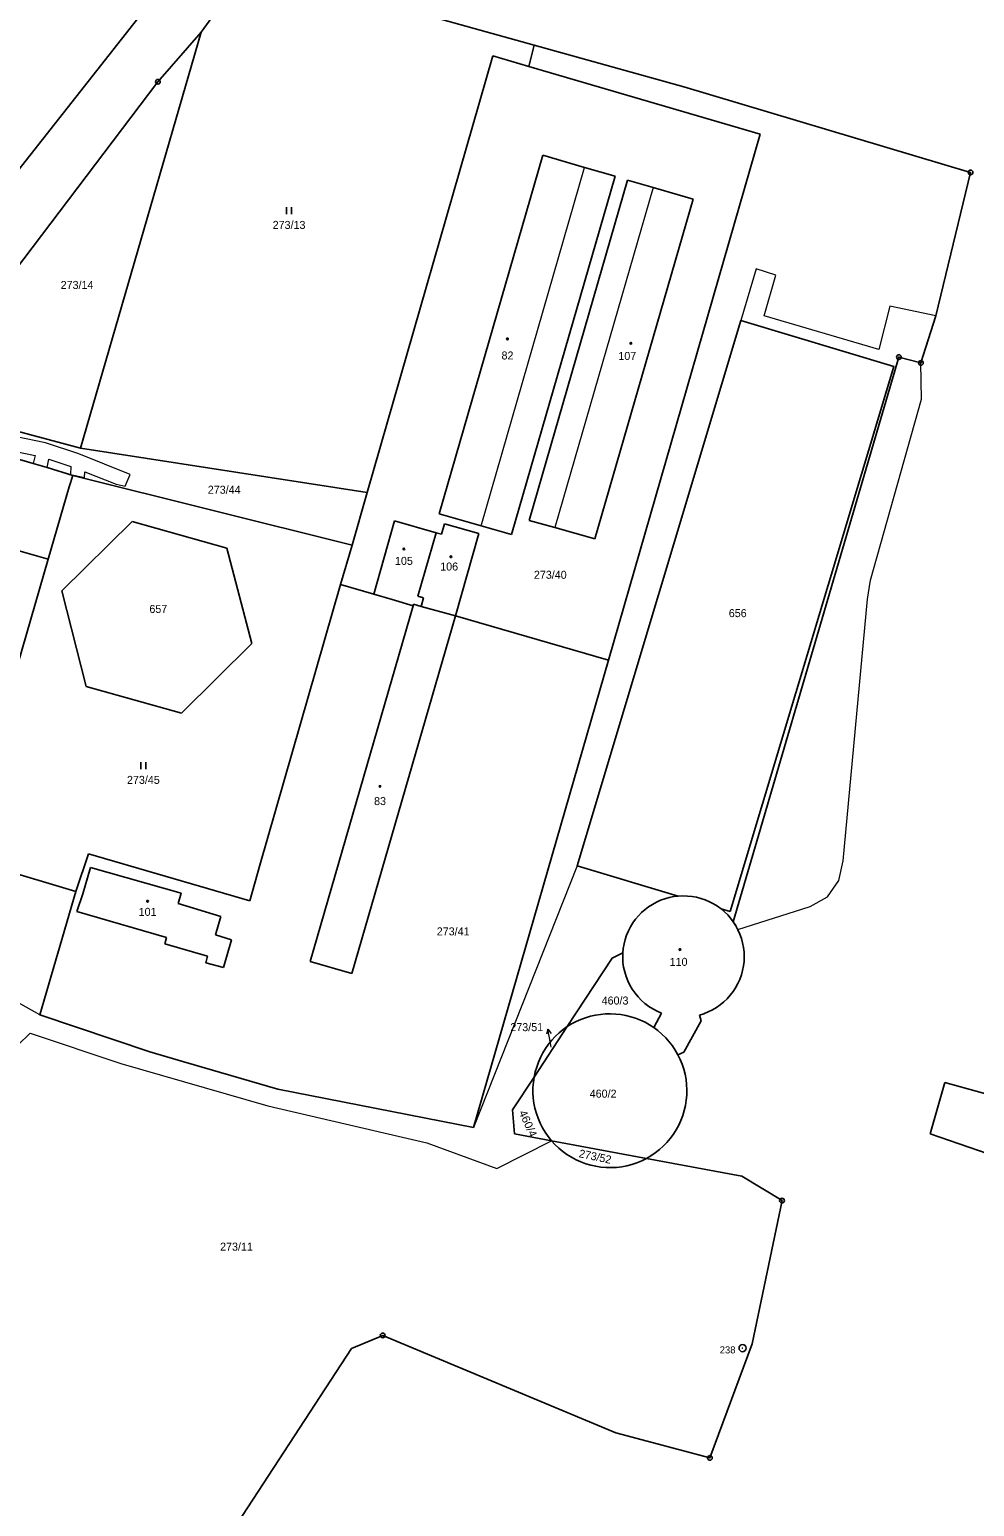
# Model space of a CAD drawing. Extents: x -759947 to -757003, y -1019641 to -1017100.
# Drawn here: x -758700 to -758499.4, y -1018436.3 to -1018122.6 of the extents above; entities that cross this region are included whole.
import ezdxf
from ezdxf.enums import TextEntityAlignment as Align

# ---------------------------------------------------------------- set-up
doc = ezdxf.new("R2010")
doc.units = 0
doc.header["$LTSCALE"] = 0.68
for name, color, linetype, lineweight in [('1', 7, 'Continuous', 25), ('13', 7, 'Continuous', 13), ('3', 7, 'Continuous', 25), ('4', 7, 'Continuous', 13), ('5', 7, 'Continuous', 25), ('7', 7, 'Continuous', 13), ('8', 7, 'Continuous', 25)]:
    doc.layers.add(name, color=color, linetype=linetype, lineweight=lineweight)
doc.layers.add('2', color=7, linetype='Continuous')

msp = doc.modelspace()

# ---------------------------------------------------------------- linework, layer by layer
at = {"layer": '1'}
for p, q in [((-758736.22, -1018195.55), (-758665.13, -1018105.17)), ((-758653.11, -1018108.83), (-758663.54, -1018123.19)), ((-758620.1, -1018118.37), (-758592.84, -1018125.96)), ((-758689.17, -1018211.55), (-758663.54, -1018123.19)), ((-758663.54, -1018123.19), (-758672.72, -1018133.73)), ((-758592.84, -1018125.96), (-758594, -1018130.48)), ((-758592.84, -1018125.96), (-758561.11, -1018134.79)), ((-758601.62, -1018128.24), (-758628.32, -1018220.98)), ((-758594, -1018130.48), (-758601.62, -1018128.24)), ((-758544.89, -1018144.88), (-758594, -1018130.48)), ((-758672.72, -1018133.73), (-758724.51, -1018202.05)), ((-758500.24, -1018152.97), (-758561.11, -1018134.79)), ((-758577.08, -1018256.57), (-758544.89, -1018144.88)), ((-758591.02, -1018149.28), (-758613.02, -1018225.48)), ((-758582.19, -1018151.92), (-758591.02, -1018149.28)), ((-758575.69, -1018153.75), (-758582.19, -1018151.92)), ((-758597.66, -1018229.89), (-758575.69, -1018153.75)), ((-758593.91, -1018226.88), (-758573.04, -1018154.62)), ((-758573.04, -1018154.62), (-758567.58, -1018156.21)), ((-758507.63, -1018183.46), (-758500.24, -1018152.97)), ((-758567.58, -1018156.21), (-758559.12, -1018158.67)), ((-758559.12, -1018158.67), (-758579.95, -1018230.83)), ((-758583.73, -1018300.25), (-758549.02, -1018184.43)), ((-758549.02, -1018184.43), (-758516.53, -1018194.17)), ((-758510.76, -1018193.44), (-758507.63, -1018183.46)), ((-758515.43, -1018192.19), (-758550.6, -1018312.14)), ((-758515.43, -1018192.19), (-758510.76, -1018193.44)), ((-758516.53, -1018194.17), (-758551.23, -1018309.99)), ((-758689.17, -1018211.55), (-758724.51, -1018202.05)), ((-758689.17, -1018211.55), (-758628.32, -1018220.98)), ((-758706.19, -1018212.74), (-758699.16, -1018214.78)), ((-758699.16, -1018214.78), (-758696.23, -1018215.67)), ((-758696.23, -1018215.67), (-758690.8, -1018217.33)), ((-758690.8, -1018217.33), (-758691.52, -1018219.77)), ((-758690.8, -1018217.33), (-758631.52, -1018232.12)), ((-758691.52, -1018219.77), (-758695.99, -1018235.12)), ((-758628.32, -1018220.98), (-758631.52, -1018232.12)), ((-758678.2, -1018227.14), (-758693.13, -1018241.87)), ((-758658.1, -1018232.78), (-758678.2, -1018227.14)), ((-758622.47, -1018227), (-758626.91, -1018242.56)), ((-758613.68, -1018229.51), (-758622.47, -1018227)), ((-758613.02, -1018225.48), (-758604.14, -1018228.03)), ((-758588.45, -1018228.43), (-758593.91, -1018226.88)), ((-758613.68, -1018229.51), (-758617.56, -1018242.97)), ((-758613.68, -1018229.51), (-758612.52, -1018229.84)), ((-758612.52, -1018229.84), (-758611.89, -1018227.63)), ((-758611.89, -1018227.63), (-758604.59, -1018229.68)), ((-758604.59, -1018229.68), (-758609.56, -1018247.18)), ((-758604.14, -1018228.03), (-758597.66, -1018229.89)), ((-758579.95, -1018230.83), (-758588.45, -1018228.43)), ((-758702.45, -1018233.28), (-758695.99, -1018235.12)), ((-758652.8, -1018253.02), (-758658.1, -1018232.78)), ((-758631.52, -1018232.12), (-758633.95, -1018240.53)), ((-758695.99, -1018235.12), (-758702.48, -1018257.43)), ((-758693.13, -1018241.87), (-758687.95, -1018262.19)), ((-758633.95, -1018240.53), (-758651.06, -1018300.15)), ((-758626.91, -1018242.56), (-758633.95, -1018240.53)), ((-758623.03, -1018243.68), (-758626.91, -1018242.56)), ((-758617.56, -1018242.97), (-758616.36, -1018243.3)), ((-758640.38, -1018320.61), (-758618.55, -1018245)), ((-758618.55, -1018245), (-758623.03, -1018243.68)), ((-758618.46, -1018244.71), (-758618.55, -1018245)), ((-758616.87, -1018245.15), (-758618.46, -1018244.71)), ((-758616.36, -1018243.3), (-758616.87, -1018245.15)), ((-758616.87, -1018245.15), (-758609.56, -1018247.18)), ((-758631.57, -1018323.1), (-758609.56, -1018247.18)), ((-758609.56, -1018247.18), (-758577.08, -1018256.57)), ((-758667.73, -1018267.8), (-758652.8, -1018253.02)), ((-758605.7, -1018355.81), (-758577.08, -1018256.57)), ((-758687.95, -1018262.19), (-758667.73, -1018267.8)), ((-758714.48, -1018298.45), (-758690.12, -1018305.73)), ((-758687.47, -1018297.72), (-758690.12, -1018305.73)), ((-758687.47, -1018297.72), (-758653.21, -1018307.72)), ((-758687.03, -1018300.58), (-758688.63, -1018306.18)), ((-758653.21, -1018307.72), (-758651.06, -1018300.15)), ((-758562.26, -1018306.69), (-758583.73, -1018300.25)), ((-758690.12, -1018305.73), (-758697.77, -1018331.94)), ((-758688.63, -1018306.18), (-758689.94, -1018309.94)), ((-758659.39, -1018311.02), (-758668.43, -1018308.27)), ((-758689.94, -1018309.94), (-758670.87, -1018315.5)), ((-758660.52, -1018314.91), (-758659.39, -1018311.02)), ((-758551.23, -1018309.99), (-758553.18, -1018309.41)), ((-758660.52, -1018314.91), (-758657.07, -1018315.95)), ((-758670.87, -1018315.5), (-758671.24, -1018316.83)), ((-758671.24, -1018316.83), (-758662.19, -1018319.47)), ((-758658.82, -1018321.89), (-758657.07, -1018315.95)), ((-758662.19, -1018319.47), (-758662.57, -1018320.83)), ((-758662.57, -1018320.83), (-758658.82, -1018321.89)), ((-758631.57, -1018323.1), (-758640.38, -1018320.61)), ((-758576.27, -1018319.85), (-758585.84, -1018334.42)), ((-758574.04, -1018318.75), (-758576.27, -1018319.85)), ((-758674.43, -1018339.76), (-758697.77, -1018331.94)), ((-758565.84, -1018331.55), (-758567.47, -1018334.6)), ((-758561.1, -1018339.83), (-758557.39, -1018333.21)), ((-758557.39, -1018333.21), (-758557.77, -1018331.97)), ((-758585.84, -1018334.42), (-758592.86, -1018345.12)), ((-758667.18, -1018341.89), (-758674.43, -1018339.76)), ((-758562.34, -1018340.38), (-758561.1, -1018339.83)), ((-758647.29, -1018347.73), (-758667.18, -1018341.89)), ((-758592.86, -1018345.12), (-758597.45, -1018352.12)), ((-758505.66, -1018346.27), (-758508.84, -1018357.21)), ((-758485.33, -1018351.92), (-758505.66, -1018346.27)), ((-758647.29, -1018347.73), (-758605.7, -1018355.81)), ((-758597.03, -1018357.19), (-758597.45, -1018352.12)), ((-758597.03, -1018357.19), (-758589.19, -1018358.65)), ((-758589.19, -1018358.65), (-758569.04, -1018362.41)), ((-758508.84, -1018357.21), (-758475.38, -1018368.74)), ((-758569.04, -1018362.41), (-758548.75, -1018366.2)), ((-758540.25, -1018371.37), (-758548.75, -1018366.2)), ((-758546.59, -1018401.82), (-758540.25, -1018371.37)), ((-758631.61, -1018402.81), (-758668.79, -1018459.65)), ((-758631.61, -1018402.81), (-758625.01, -1018400.02)), ((-758575.51, -1018420.67), (-758625.01, -1018400.02)), ((-758555.55, -1018426.01), (-758546.59, -1018401.82)), ((-758575.51, -1018420.67), (-758555.55, -1018426.01))]:
    msp.add_line(p, q, dxfattribs=at)
for points in [[(-758668.43, -1018308.27), (-758667.8, -1018306.09), (-758687.03, -1018300.58)], [(-758574.04, -1018318.75), (-758573.946, -1018317.787), (-758573.78, -1018316.835), (-758573.543, -1018315.897), (-758573.236, -1018314.98), (-758572.861, -1018314.088), (-758572.42, -1018313.228), (-758571.916, -1018312.402), (-758571.351, -1018311.617), (-758570.729, -1018310.876), (-758570.054, -1018310.185), (-758569.328, -1018309.545), (-758568.556, -1018308.962), (-758567.743, -1018308.439), (-758566.893, -1018307.978), (-758566.01, -1018307.583), (-758565.1, -1018307.254), (-758564.169, -1018306.995), (-758563.22, -1018306.807), (-758562.26, -1018306.69)], [(-758562.26, -1018306.69), (-758561.291, -1018306.643), (-758560.32, -1018306.669), (-758559.355, -1018306.768), (-758558.4, -1018306.939), (-758557.46, -1018307.183), (-758556.542, -1018307.496), (-758555.649, -1018307.878), (-758554.788, -1018308.326), (-758553.964, -1018308.838), (-758553.18, -1018309.41)], [(-758553.18, -1018309.41), (-758552.458, -1018310.016), (-758551.785, -1018310.676), (-758551.165, -1018311.385), (-758550.6, -1018312.14)], [(-758557.77, -1018331.97), (-758556.829, -1018331.673), (-758555.912, -1018331.305), (-758555.027, -1018330.869), (-758554.178, -1018330.365), (-758553.37, -1018329.799), (-758552.607, -1018329.172), (-758551.895, -1018328.489), (-758551.237, -1018327.753), (-758550.637, -1018326.969), (-758550.099, -1018326.141), (-758549.625, -1018325.275), (-758549.22, -1018324.375), (-758548.884, -1018323.447), (-758548.62, -1018322.496), (-758548.43, -1018321.527), (-758548.315, -1018320.547), (-758548.275, -1018319.56), (-758548.31, -1018318.574), (-758548.421, -1018317.593), (-758548.606, -1018316.623), (-758548.865, -1018315.671), (-758549.196, -1018314.741), (-758549.597, -1018313.839), (-758550.066, -1018312.97), (-758550.6, -1018312.14)], [(-758574.04, -1018318.75), (-758574.061, -1018319.765), (-758574.002, -1018320.779), (-758573.864, -1018321.786), (-758573.647, -1018322.778), (-758573.352, -1018323.75), (-758572.982, -1018324.696), (-758572.539, -1018325.61), (-758572.025, -1018326.486), (-758571.444, -1018327.319), (-758570.799, -1018328.104), (-758570.095, -1018328.835), (-758569.335, -1018329.509), (-758568.524, -1018330.121), (-758567.668, -1018330.667), (-758566.771, -1018331.145), (-758565.84, -1018331.55)], [(-758567.47, -1018334.6), (-758568.38, -1018334.012), (-758569.328, -1018333.486), (-758570.308, -1018333.024), (-758571.316, -1018332.628), (-758572.349, -1018332.299), (-758573.401, -1018332.04), (-758574.468, -1018331.851), (-758575.545, -1018331.733), (-758576.627, -1018331.686), (-758577.711, -1018331.711), (-758578.79, -1018331.808), (-758579.86, -1018331.977), (-758580.917, -1018332.215), (-758581.956, -1018332.524), (-758582.972, -1018332.9), (-758583.961, -1018333.343), (-758584.918, -1018333.85), (-758585.84, -1018334.42)], [(-758592.86, -1018345.12), (-758592.628, -1018344.049), (-758592.326, -1018342.997), (-758591.953, -1018341.967), (-758591.513, -1018340.964), (-758591.007, -1018339.992), (-758590.437, -1018339.057), (-758589.806, -1018338.162), (-758589.116, -1018337.31), (-758588.372, -1018336.507), (-758587.575, -1018335.756), (-758586.73, -1018335.059), (-758585.84, -1018334.42)], [(-758562.34, -1018340.38), (-758562.898, -1018339.416), (-758563.519, -1018338.491), (-758564.201, -1018337.61), (-758564.94, -1018336.776), (-758565.734, -1018335.995), (-758566.579, -1018335.268), (-758567.47, -1018334.6)], [(-758562.34, -1018340.38), (-758561.854, -1018341.379), (-758561.437, -1018342.408), (-758561.091, -1018343.464), (-758560.817, -1018344.54), (-758560.617, -1018345.633), (-758560.492, -1018346.737), (-758560.442, -1018347.847), (-758560.468, -1018348.957), (-758560.569, -1018350.063), (-758560.745, -1018351.16), (-758560.995, -1018352.242), (-758561.319, -1018353.305), (-758561.713, -1018354.343), (-758562.178, -1018355.352), (-758562.709, -1018356.328), (-758563.306, -1018357.264), (-758563.966, -1018358.159), (-758564.684, -1018359.006), (-758565.458, -1018359.802), (-758566.285, -1018360.544), (-758567.16, -1018361.228), (-758568.08, -1018361.851), (-758569.04, -1018362.41)], [(-758592.86, -1018345.12), (-758593.02, -1018346.223), (-758593.105, -1018347.334), (-758593.114, -1018348.448), (-758593.047, -1018349.56), (-758592.904, -1018350.666), (-758592.687, -1018351.758), (-758592.395, -1018352.834), (-758592.03, -1018353.887), (-758591.595, -1018354.913), (-758591.091, -1018355.906), (-758590.52, -1018356.864), (-758589.886, -1018357.779), (-758589.19, -1018358.65)], [(-758589.19, -1018358.65), (-758588.442, -1018359.467), (-758587.64, -1018360.232), (-758586.788, -1018360.94), (-758585.89, -1018361.589), (-758584.951, -1018362.176), (-758583.973, -1018362.697), (-758582.962, -1018363.151), (-758581.923, -1018363.535), (-758580.861, -1018363.848), (-758579.779, -1018364.088), (-758578.684, -1018364.255), (-758577.58, -1018364.346), (-758576.472, -1018364.362), (-758575.365, -1018364.303), (-758574.266, -1018364.17), (-758573.177, -1018363.961), (-758572.106, -1018363.68), (-758571.056, -1018363.326), (-758570.032, -1018362.902), (-758569.04, -1018362.41)]]:
    msp.add_lwpolyline(points, dxfattribs=at)
at = {"layer": '13'}
for points in [[(-758549.63, -1018313.77), (-758534.24, -1018308.87), (-758530.63, -1018306.85), (-758528.2, -1018303.36), (-758527.24, -1018299.2), (-758522.14, -1018243.62), (-758521.49, -1018239.57), (-758510.65, -1018201.14), (-758510.76, -1018193.44), (-758507.63, -1018183.46), (-758517.4, -1018181.35), (-758519.71, -1018190.56), (-758544.03, -1018183.46), (-758541.56, -1018174.77), (-758545.73, -1018173.45), (-758549.02, -1018184.43), (-758516.53, -1018194.17), (-758551.23, -1018309.99), (-758553.18, -1018309.41), (-758552.458, -1018310.016), (-758551.785, -1018310.676), (-758551.165, -1018311.385), (-758550.6, -1018312.14), (-758550.084, -1018312.937)], [(-758696.56, -1018210.38), (-758706.92, -1018208.27), (-758725.64, -1018203.6), (-758727.29, -1018205.87), (-758709, -1018210.96), (-758709.12, -1018211.73), (-758706.19, -1018212.74), (-758706.01, -1018211.63), (-758698.79, -1018213.1), (-758699.16, -1018214.78), (-758696.23, -1018215.67), (-758695.84, -1018213.89), (-758691.22, -1018215.44), (-758691.28, -1018217.12), (-758688.33, -1018217.76), (-758688.21, -1018216.55), (-758681.61, -1018219.22), (-758679.64, -1018219.65), (-758678.63, -1018217.14), (-758689.47, -1018212.75)]]:
    msp.add_lwpolyline(points, close=True, dxfattribs=at)
msp.add_lwpolyline([(-758702.47, -1018338.38), (-758699.81, -1018335.83), (-758680.56, -1018342.24), (-758649.39, -1018351.25), (-758615.66, -1018359.09), (-758600.76, -1018364.54), (-758589.19, -1018358.65), (-758597.03, -1018357.19), (-758597.45, -1018352.12), (-758592.86, -1018345.12), (-758592.628, -1018344.049), (-758592.326, -1018342.997), (-758591.953, -1018341.967), (-758591.513, -1018340.964), (-758591.007, -1018339.992), (-758590.437, -1018339.057), (-758589.806, -1018338.162), (-758589.116, -1018337.31), (-758588.372, -1018336.507), (-758587.575, -1018335.756), (-758586.73, -1018335.059), (-758585.84, -1018334.42), (-758576.27, -1018319.85), (-758574.04, -1018318.75), (-758573.946, -1018317.787), (-758573.78, -1018316.835), (-758573.543, -1018315.897), (-758573.236, -1018314.98), (-758572.861, -1018314.088), (-758572.42, -1018313.228), (-758571.916, -1018312.402), (-758571.351, -1018311.617), (-758570.729, -1018310.876), (-758570.054, -1018310.185), (-758569.328, -1018309.545), (-758568.556, -1018308.962), (-758567.743, -1018308.439), (-758566.893, -1018307.978), (-758566.01, -1018307.583), (-758565.1, -1018307.254), (-758564.169, -1018306.995), (-758563.22, -1018306.807), (-758562.26, -1018306.69), (-758583.73, -1018300.25), (-758605.7, -1018355.81), (-758647.29, -1018347.73), (-758667.18, -1018341.89), (-758674.43, -1018339.76), (-758697.77, -1018331.94), (-758720.4, -1018319.27)], dxfattribs=at)
at = {"layer": '3'}
for p, q in [((-758645.391, -1018161.85), (-758645.391, -1018160.35)), ((-758644.39, -1018161.85), (-758644.39, -1018160.35)), ((-758676.311, -1018279.73), (-758676.311, -1018278.23)), ((-758675.31, -1018279.73), (-758675.31, -1018278.23))]:
    msp.add_line(p, q, dxfattribs=at)
at = {"layer": '4'}
for p, q in [((-758604.14, -1018228.03), (-758582.19, -1018151.92)), ((-758567.58, -1018156.21), (-758588.45, -1018228.43))]:
    msp.add_line(p, q, dxfattribs=at)
at = {"layer": '5'}
for centre in [(-758598.5268, -1018188.3292), (-758572.3368, -1018189.2692), (-758620.5068, -1018232.9492), (-758610.5268, -1018234.6092), (-758625.5768, -1018283.3892), (-758674.9168, -1018307.7692), (-758561.8968, -1018318.0392)]:
    msp.add_circle(centre, 0.175, dxfattribs=at)
at = {"layer": '7'}
msp.add_line((-758589.941, -1018334.945), (-758590.26, -1018336.018), dxfattribs=at)
msp.add_lwpolyline([(-758589.27, -1018338.75), (-758589.42, -1018337.9), (-758589.941, -1018334.945), (-758589.274, -1018335.844)], dxfattribs=at)
at = {"layer": '8'}
for centre, radius in [((-758672.72, -1018133.7299), 0.5), ((-758672.72, -1018133.7299), 0.0303), ((-758500.24, -1018152.9699), 0.5), ((-758500.24, -1018152.9699), 0.0303), ((-758515.43, -1018192.1899), 0.5), ((-758515.43, -1018192.1899), 0.0303), ((-758510.76, -1018193.4399), 0.5), ((-758510.76, -1018193.4399), 0.0303), ((-758540.25, -1018371.3699), 0.5), ((-758540.25, -1018371.3699), 0.0303), ((-758625.01, -1018400.0199), 0.5), ((-758625.01, -1018400.0199), 0.0303), ((-758548.63, -1018402.7098), 0.75), ((-758548.63, -1018402.7098), 0.03), ((-758555.55, -1018426.0099), 0.5), ((-758555.55, -1018426.0099), 0.0303)]:
    msp.add_circle(centre, radius, dxfattribs=at)

# ---------------------------------------------------------------- texts
at = {"layer": '2'}
for s, p in [('273/13', (-758644.88, -1018164.975)), ('273/14', (-758689.88, -1018177.725)), ('82', (-758598.519, -1018192.705)), ('107', (-758573.089, -1018192.805)), ('273/44', (-758658.65, -1018221.225)), ('105', (-758620.499, -1018236.335)), ('106', (-758610.899, -1018237.535)), ('273/40', (-758589.43, -1018239.285)), ('657', (-758672.629, -1018246.545)), ('656', (-758549.649, -1018247.435)), ('273/45', (-758675.8, -1018282.855)), ('83', (-758625.569, -1018287.355)), ('101', (-758674.909, -1018310.885)), ('273/41', (-758610.05, -1018315.035)), ('110', (-758562.209, -1018321.505)), ('460/3', (-758575.69, -1018329.725)), ('460/2', (-758578.22, -1018349.505)), ('273/11', (-758656.04, -1018382.005))]:
    msp.add_text(s, height=1.7, dxfattribs=at).set_placement(p, align=Align.CENTER)
msp.add_text('273/51', height=1.7, dxfattribs=at).set_placement((-758590.959, -1018335.375), align=Align.RIGHT)
at = {"layer": '2', "width": 1.05}
msp.add_text('460/4', height=1.7, rotation=294, dxfattribs=at).set_placement((-758594.9389, -1018355.3483), align=Align.CENTER)
at = {"layer": '2'}
msp.add_text('273/52', height=1.7, rotation=348, dxfattribs=at).set_placement((-758580.0682, -1018362.8449), align=Align.CENTER)
at = {"layer": '8'}
msp.add_text('238', height=1.5, dxfattribs=at).set_placement((-758550.129, -1018403.827), align=Align.RIGHT)

doc.saveas('drawing.dxf')
